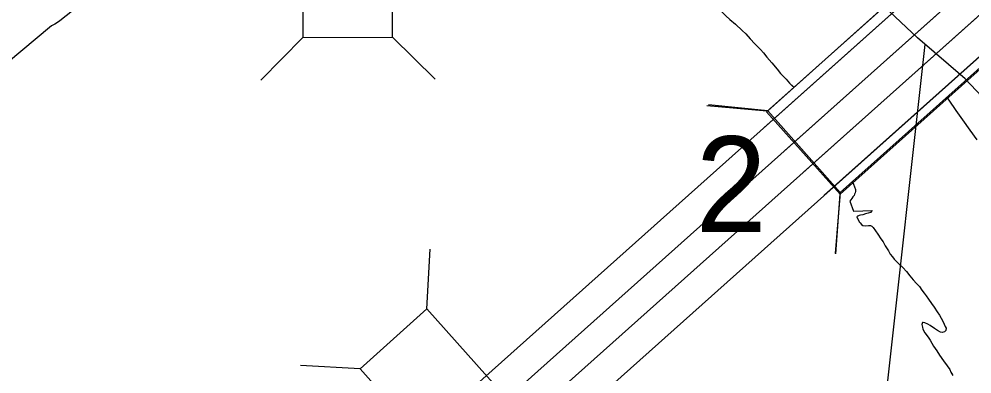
# Model space of a CAD drawing. Extents: x 535214 to 694517, y 381272 to 484355.
# Drawn here: x 544277 to 546381, y 458296 to 459079 of the extents above; entities that cross this region are included whole.
import ezdxf

# ---------------------------------------------------------------- set-up
doc = ezdxf.new("R2010")
doc.units = 0
for name, color, linetype in [('Level 15', 7, 'Continuous'), ('Level 19', 7, 'Continuous'), ('Level 2', 7, 'Continuous'), ('Level 20', 7, 'Continuous'), ('Level 23', 7, 'Continuous'), ('Level 6', 7, 'Continuous'), ('Level 9', 7, 'Continuous')]:
    doc.layers.add(name, color=color, linetype=linetype)

msp = doc.modelspace()

# ---------------------------------------------------------------- linework, layer by layer
at = {"layer": 'Level 15'}
for points in [[(544395.3, 459097.3), (544367.5, 459074.8), (544364.7, 459073.1), (544356.3, 459067.5), (544348.8, 459063.7)], [(544348.8, 459063.7), (543900.7, 458689.8)]]:
    msp.add_lwpolyline(points, dxfattribs=at)
at = {"layer": 'Level 19'}
for points in [[(546684.3, 459520), (545143.2, 458144.5)], [(546730.2, 459468.9), (545188.9, 458093.2)], [(546772, 459422.3), (545230.5, 458046.5)], [(546657.7, 459404.2), (545967.6, 458788.2)], [(546817.9, 459371.2), (545276.3, 457995.2)], [(546699.4, 459357.6), (546009.2, 458741.6)], [(546471.8, 459330.4), (545921.4, 458839.1)], [(546748.6, 459309.4), (546055.2, 458690.5)]]:
    msp.add_lwpolyline(points, dxfattribs=at)
at = {"layer": 'Level 2'}
for points in [[(546325.7, 458906.1), (546330.6, 458900), (546345.7, 458877), (546360.7, 458856.6), (546376.8, 458834.1), (546392.3, 458812.6)], [(546329.7, 458901.1), (546330.6, 458900), (546345.7, 458877), (546360.7, 458856.6), (546376.8, 458834.1), (546392.3, 458812.6)]]:
    msp.add_lwpolyline(points, dxfattribs=at)
at = {"layer": 'Level 20'}
for p, q in [((544904.1, 459038.2), (544811.1, 458944.5)), ((545102.1, 459038.9), (545195.8, 458946)), ((545795.9, 458888.3), (545928.1, 458876.8)), ((545930.3, 458876.6), (545799.6, 458889.5)), ((545927.9, 458874.5), (546090.4, 458692.5)), ((546090.4, 458696.2), (546079.4, 458561.8)), ((546081.1, 458561.1), (546090.4, 458692.5)), ((545177.9, 458439.5), (545185.4, 458571.3)), ((545030.2, 458307.7), (544898.4, 458315.2))]:
    msp.add_line(p, q, dxfattribs=at)
for points in [[(544901.9, 459632.2), (544904.1, 459038.2), (545102.1, 459038.9), (545099.9, 459632.9)], [(545930.3, 458876.6), (546668.5, 459537.5), (546830.5, 459357.1), (546090.4, 458696.2)], [(545573.4, 457996.4), (545177.9, 458439.5), (545030.2, 458307.7), (545425.7, 457864.5)]]:
    msp.add_lwpolyline(points, close=True, dxfattribs=at)
for points in [[(546670.1, 459537), (545927.9, 458874.5)], [(546832.5, 459355), (546090.4, 458692.5)]]:
    msp.add_lwpolyline(points, dxfattribs=at)
at = {"layer": 'Level 23'}
msp.add_line((546149.3, 457861.5), (546277.9, 459022.8), dxfattribs=at)
at = {"layer": 'Level 6'}
for points in [[(546859.7, 458267.4), (546806.6, 458380.7), (546781.4, 458430.3), (546736.1, 458511.3), (546627.3, 458663), (546559.5, 458744.8), (546489.4, 458817.1), (546366.4, 458947), (546261.1, 459037.3), (546113.4, 459177), (545930.9, 459367.3), (545850.8, 459452.2), (545666.6, 459629.7), (545602.1, 459691), (545585.2, 459710.8), (545529, 459767.9), (545433.2, 459853.1), (545322.1, 459945.2), (545175.8, 460062.8), (545068.8, 460141.3)], [(546489.4, 458817.1), (546366.4, 458947), (546261.1, 459037.3), (546113.4, 459177)]]:
    msp.add_lwpolyline(points, dxfattribs=at)
at = {"layer": 'Level 9'}
for points in [[(545487, 459475.4), (545648.2, 459303.9), (545798.5, 459130.3), (545812, 459112.3), (545817.5, 459106.8), (545829.5, 459093.9), (545838, 459086.4), (545847, 459077.9), (545859.1, 459067.9), (545874.1, 459054), (545882.1, 459046), (545891.6, 459035.5), (545902.1, 459024.6), (545914.1, 459011.6), (545920.7, 459004.1), (545928.2, 458994.6), (545939.7, 458982.1), (545951.2, 458968.7), (545958.7, 458959.2), (545970.8, 458946.2), (545978.3, 458937.2), (545986.9, 458929.2)], [(545505.8, 459455.5), (545648.2, 459303.9), (545798.5, 459130.3), (545812, 459112.3), (545817.5, 459106.8), (545829.5, 459093.9), (545838, 459086.4), (545847, 459077.9), (545859.1, 459067.9), (545874.1, 459054), (545882.1, 459046), (545891.6, 459035.5), (545902.1, 459024.6), (545914.1, 459011.6), (545920.7, 459004.1), (545928.2, 458994.6), (545939.7, 458982.1), (545951.2, 458968.7), (545958.7, 458959.2), (545970.8, 458946.2), (545978.3, 458937.2), (545985.7, 458930.2)], [(546116.9, 458722.2), (546119.8, 458714.5), (546122.3, 458709), (546124.3, 458703), (546124.3, 458698.5), (546123.3, 458695.5), (546121.9, 458693), (546120.9, 458689.5), (546118.4, 458686.5), (546115.9, 458682.9), (546113.9, 458680.4), (546111.4, 458677.4), (546120, 458655.4), (546160.9, 458656.6), (546157.4, 458652.6), (546152, 458650.5), (546146, 458649), (546140, 458647.5), (546135, 458646.5), (546132, 458645.5), (546129.5, 458644.5), (546127, 458642.4), (546132.1, 458632), (546134.1, 458629.5), (546137.6, 458626), (546140.6, 458623.5), (546146.6, 458623), (546153, 458623.5), (546157, 458623.5), (546160.5, 458622), (546163, 458619.1), (546168.6, 458612.1), (546173.6, 458604.6), (546180.1, 458594.1), (546185.1, 458587.6), (546189.6, 458578.6), (546197.2, 458567.6), (546200.7, 458560.6), (546205.7, 458554.6)], [(546118.9, 458716.8), (546119.8, 458714.5), (546122.3, 458709), (546124.3, 458703), (546124.3, 458698.5), (546123.3, 458695.5), (546121.9, 458693), (546120.9, 458689.5), (546118.4, 458686.5), (546115.9, 458682.9), (546113.9, 458680.4), (546111.4, 458677.4), (546120, 458655.4), (546160.9, 458656.6), (546157.4, 458652.6), (546152, 458650.5), (546146, 458649), (546140, 458647.5), (546135, 458646.5), (546132, 458645.5), (546129.5, 458644.5), (546127, 458642.4), (546132.1, 458632), (546134.1, 458629.5), (546137.6, 458626), (546140.6, 458623.5), (546146.6, 458623), (546153, 458623.5), (546157, 458623.5), (546160.5, 458622), (546163, 458619.1), (546168.6, 458612.1), (546173.6, 458604.6), (546180.1, 458594.1), (546185.1, 458587.6), (546189.6, 458578.6), (546197.2, 458567.6), (546200.7, 458560.6), (546205.7, 458554.6)], [(546205.7, 458554.6), (546209.7, 458549.6), (546220.7, 458538.7), (546228.7, 458530.7), (546236.7, 458522.2), (546244.3, 458512.7), (546251.8, 458503.7), (546258.8, 458495.8), (546265.3, 458488.8), (546270.8, 458480.8), (546275.8, 458474.3), (546280.3, 458468.3), (546285.4, 458460.8), (546291.9, 458451.8), (546297.9, 458443.3), (546304.4, 458432.9), (546309.4, 458425.9), (546313.4, 458418.9), (546318, 458410.9), (546322.5, 458400.9), (546324, 458396.9), (546323.5, 458391.9), (546320.5, 458389.4), (546315.6, 458387.3), (546311.6, 458388.3), (546305.1, 458391.8), (546298.6, 458396.3), (546289.1, 458402.8), (546283.6, 458406.2), (546277.6, 458408.7), (546273.6, 458409.7), (546272.1, 458409.7), (546270.6, 458405.2), (546272.1, 458399.7), (546273.1, 458394.7), (546277.6, 458386.7), (546284.7, 458377.2), (546288.7, 458370.7), (546296.7, 458357.2), (546303.7, 458347.3), (546309.8, 458337.3), (546318.3, 458324.8), (546326.8, 458314.3), (546332.3, 458305.8), (546334.8, 458300.3), (546336.8, 458297.1)], [(546205.7, 458554.6), (546209.7, 458549.6), (546220.7, 458538.7), (546228.7, 458530.7), (546236.7, 458522.2), (546244.3, 458512.7), (546251.8, 458503.7), (546258.8, 458495.8), (546265.3, 458488.8), (546270.8, 458480.8), (546275.8, 458474.3), (546280.3, 458468.3), (546285.4, 458460.8), (546291.9, 458451.8), (546297.9, 458443.3), (546304.4, 458432.9), (546309.4, 458425.9), (546313.4, 458418.9), (546318, 458410.9), (546322.5, 458400.9), (546324, 458396.9), (546323.5, 458391.9), (546320.5, 458389.4), (546315.6, 458387.3), (546311.6, 458388.3), (546305.1, 458391.8), (546298.6, 458396.3), (546289.1, 458402.8), (546283.6, 458406.2), (546277.6, 458408.7), (546273.6, 458409.7), (546272.1, 458409.7), (546270.6, 458405.2), (546272.1, 458399.7), (546273.1, 458394.7), (546277.6, 458386.7), (546284.7, 458377.2), (546288.7, 458370.7), (546296.7, 458357.2), (546303.7, 458347.3), (546309.8, 458337.3), (546318.3, 458324.8), (546326.8, 458314.3), (546332.3, 458305.8), (546334.8, 458300.3), (546339.4, 458292.8)]]:
    msp.add_lwpolyline(points, dxfattribs=at)

# ---------------------------------------------------------------- texts
at = {"layer": 'Level 20'}
msp.add_text('2', height=211.2, dxfattribs=at).set_placement((545771.2, 458609.1))

doc.saveas('drawing.dxf')
